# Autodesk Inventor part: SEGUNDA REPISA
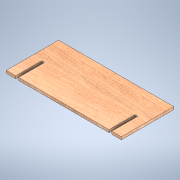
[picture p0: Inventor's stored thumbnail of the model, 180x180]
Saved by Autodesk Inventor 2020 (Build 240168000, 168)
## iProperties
Created: 2020-03
Part Number: SEGUNDA REPISA
Material: Madera (abedul)
Document SubType Name: Modeling
Designer: Arias
Density: 0.55 g/cm^3
Appearance: Abedul - Natural pulido
Author: Arias
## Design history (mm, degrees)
sketch "Boceto1"
  geometry: L1 (480, 0)-(480, -218.043); L2 (480, -218.043)-(0, -218.043); L3 (0, -218.043)-(0, 0); L4 (440, 0)-(440, -107.759); L5 (51.1, 0)-(51.1, -107.759); L6 (428.9, 0)-(428.9, -107.759); L7 (40, 0)-(40, -107.759); L8 (440, -107.759)-(428.9, -107.759); L9 (51.1, -107.759)-(40, -107.759); L10 (0, 0)-(40, 0); L11 (51.1, 0)-(428.9, 0); L12 (440, 0)-(480, 0)
  constraints: 24 end point, 6 parallel, 4 horizontal, 3 perpendicular, 2 vertical, 1 collinear
  dimensions: "d0" = 480 distance of L1.end L2.end; "d1" = 218.043 distance of L1.start L1.end; "d2" = 107.759 distance of L4.start L4.end; "d3" = 107.759 distance of L5.start L5.end; "d4" = 11.1 distance between parallel lines of L4 L6; "d5" = 11.1 distance between parallel lines of L5 L7; "d8" = 40 distance between parallel lines of L3 L7; "d9" = 400 distance between parallel lines of L4 L7
extrude "Extrusión1" new body sketch "Boceto1" distance "d6" = 11.1; taper "d7" = 0 deg
node "Sólido1"
